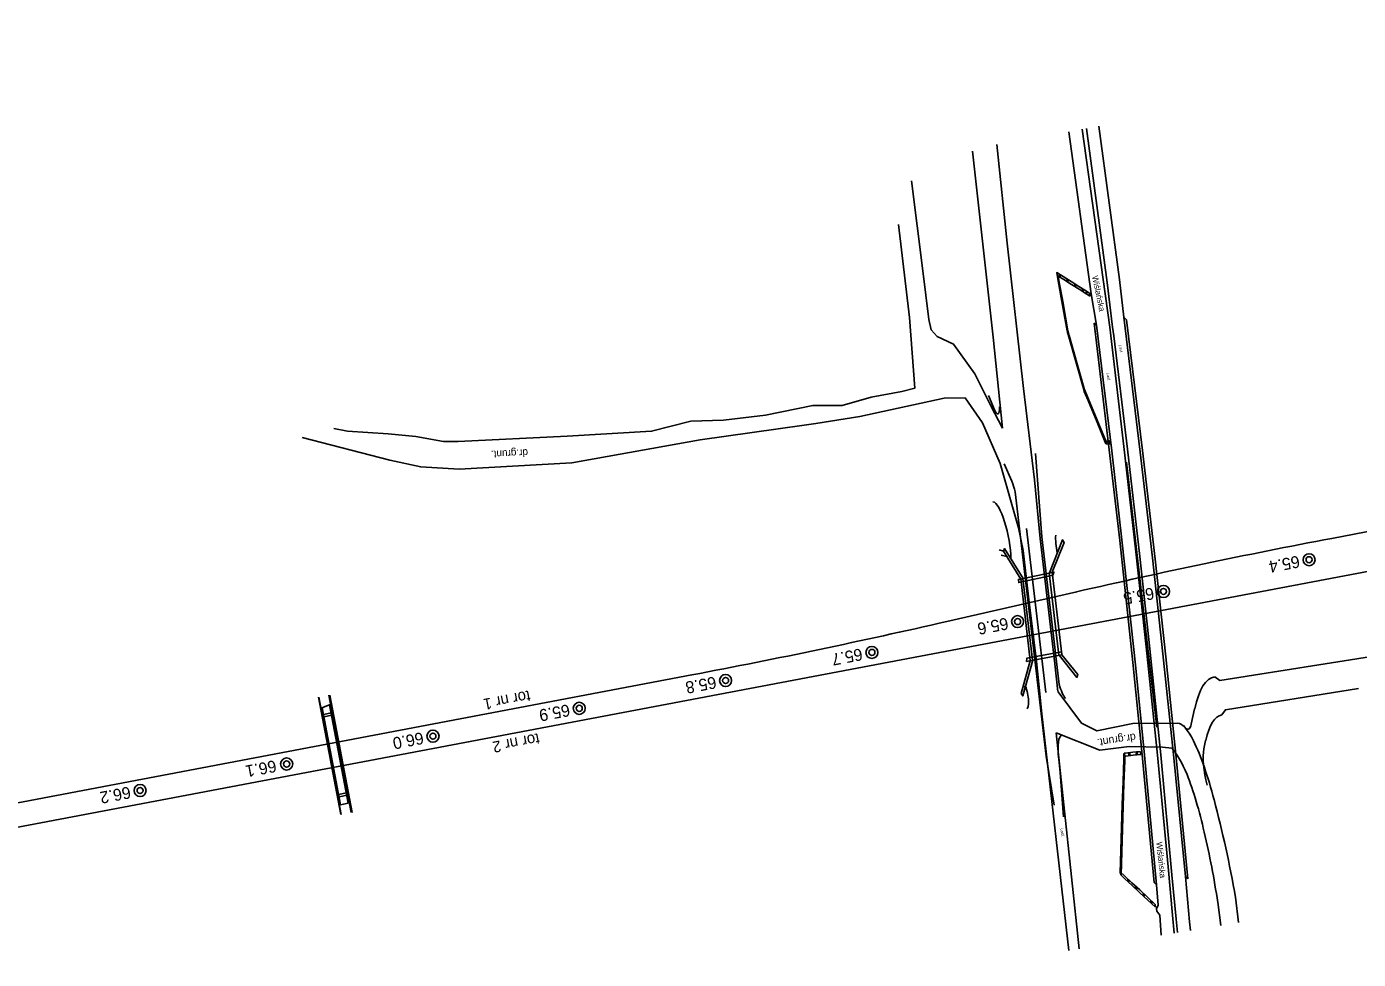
# Model space of a CAD drawing. Extents: x 6541740 to 6556805, y 5525233 to 5530361.
# Drawn here: x 6556027.8 to 6556251.3, y 5525917.2 to 5526073.7 of the extents above; entities that cross this region are included whole.
import ezdxf

# ---------------------------------------------------------------- set-up
doc = ezdxf.new("R2010")
doc.units = 0
for name, color, linetype in [('Default', 7, 'Continuous'), ('TOR_PS_OPIS_T-numeracja torow i rozjazdow', 7, 'Continuous'), ('TOR_SCH-budynki', 7, 'Continuous'), ('TOR_SCH-hektometry', 7, 'Continuous'), ('TOR_SCH-obiekty istniejace', 7, 'Continuous'), ('TOR_SCH-obiekty projektowane', 7, 'Continuous'), ('TOR_SCH-przejazdy+drogi istniejace', 7, 'Continuous'), ('TOR_SCH-przejazdy+drogi projektowane', 7, 'Continuous'), ('TOR_SCH-tory projektowane', 7, 'Continuous')]:
    doc.layers.add(name, color=color, linetype=linetype)

# ---------------------------------------------------------------- blocks, each defined once
blk = doc.blocks.new('4010_1')
at = {"layer": 'Default'}
for radius in [0.75, 0.375]:
    blk.add_circle((0, 0), radius, dxfattribs=at)

msp = doc.modelspace()

# ---------------------------------------------------------------- linework, layer by layer
at = {"layer": 'TOR_SCH-budynki'}
msp.add_line((6556222.71, 5525930.72), (6556222.31, 5525931.11), dxfattribs=at)
at = {"layer": 'TOR_SCH-obiekty istniejace'}
for p, q in [((6556200.84, 5526031.77), (6556201.47, 5526028.22)), ((6556201.13, 5526032.22), (6556201.06, 5526031.81)), ((6556201.31, 5526032.1), (6556201.24, 5526031.7)), ((6556203.1, 5526030.97), (6556201.79, 5526031.79)), ((6556203.18, 5526030.48), (6556201.88, 5526031.3)), ((6556202.43, 5526031.4), (6556202.36, 5526030.99)), ((6556202.61, 5526031.28), (6556202.55, 5526030.88)), ((6556204.41, 5526030.15), (6556203.1, 5526030.97)), ((6556201.14, 5526030.79), (6556201.6, 5526028.22)), ((6556201.2, 5526029.78), (6556201.39, 5526029.38)), ((6556201.29, 5526029.22), (6556201.49, 5526028.82)), ((6556204.48, 5526029.67), (6556203.18, 5526030.48)), ((6556203.73, 5526030.58), (6556203.66, 5526030.18)), ((6556203.91, 5526030.46), (6556203.85, 5526030.06)), ((6556205.71, 5526029.33), (6556204.41, 5526030.15)), ((6556205.77, 5526028.85), (6556204.48, 5526029.67)), ((6556205.03, 5526029.76), (6556204.97, 5526029.36)), ((6556205.22, 5526029.64), (6556205.15, 5526029.24)), ((6556205.77, 5526028.85), (6556205.71, 5526029.33)), ((6556205.71, 5526029.33), (6556206.22, 5526029.02)), ((6556205.71, 5526029.33), (6556205.77, 5526028.85)), ((6556205.77, 5526028.85), (6556206.28, 5526028.53)), ((6556206.28, 5526028.53), (6556206.22, 5526029.02)), ((6556201.6, 5526028.22), (6556201.47, 5526028.22)), ((6556201.58, 5526027.63), (6556201.47, 5526028.22)), ((6556201.47, 5526028.22), (6556201.6, 5526028.22)), ((6556202.44, 5526022.71), (6556201.58, 5526027.63)), ((6556201.7, 5526027.63), (6556201.6, 5526028.22)), ((6556202.57, 5526022.71), (6556201.7, 5526027.63)), ((6556214.73, 5526002.32), (6556211.96, 5526024.97)), ((6556211.96, 5526024.97), (6556212.41, 5526024.54)), ((6556212.41, 5526024.54), (6556215.09, 5526002.62)), ((6556202.57, 5526022.71), (6556202.44, 5526022.71)), ((6556202.55, 5526022.81), (6556202.47, 5526022.62)), ((6556202.73, 5526021.7), (6556202.47, 5526022.62)), ((6556202.81, 5526021.89), (6556202.55, 5526022.81)), ((6556207.39, 5526023.65), (6556206.99, 5526023.99)), ((6556206.99, 5526023.99), (6556209.53, 5526002.74)), ((6556209.94, 5526002.53), (6556207.39, 5526023.65)), ((6556204.02, 5526017.15), (6556202.73, 5526021.7)), ((6556204.1, 5526017.34), (6556202.81, 5526021.89)), ((6556203.43, 5526019.71), (6556203.22, 5526019.98)), ((6556203.61, 5526019.07), (6556203.4, 5526019.33)), ((6556205.31, 5526012.6), (6556204.02, 5526017.15)), ((6556205.39, 5526012.79), (6556204.1, 5526017.34)), ((6556204.72, 5526015.16), (6556204.51, 5526015.43)), ((6556204.9, 5526014.52), (6556204.69, 5526014.78)), ((6556205.39, 5526012.79), (6556205.31, 5526012.6)), ((6556205.37, 5526012.86), (6556205.33, 5526012.53)), ((6556205.97, 5526010.99), (6556205.33, 5526012.53)), ((6556206, 5526011.32), (6556205.37, 5526012.86)), ((6556207.47, 5526007.37), (6556205.97, 5526010.99)), ((6556207.5, 5526007.7), (6556206, 5526011.32)), ((6556206.72, 5526009.59), (6556206.54, 5526009.62)), ((6556206.93, 5526009.07), (6556206.75, 5526009.1)), ((6556208.97, 5526003.74), (6556207.47, 5526007.37)), ((6556209, 5526004.08), (6556207.5, 5526007.7)), ((6556208.22, 5526005.96), (6556208.04, 5526005.99)), ((6556208.43, 5526005.45), (6556208.25, 5526005.48)), ((6556209.57, 5526004.22), (6556208.94, 5526004.15)), ((6556208.94, 5526004.15), (6556209.03, 5526003.66)), ((6556209, 5526004.08), (6556208.97, 5526003.74)), ((6556209.1, 5526004.17), (6556209.06, 5526003.67)), ((6556209.57, 5526004.22), (6556209.66, 5526003.72)), ((6556209.66, 5526003.72), (6556209.03, 5526003.66)), ((6556209.53, 5526002.74), (6556211.27, 5525987.51)), ((6556211.71, 5525987.1), (6556209.94, 5526002.53)), ((6556214.73, 5526002.32), (6556216.78, 5525984.59)), ((6556215.09, 5526002.62), (6556217.2, 5525984.4)), ((6556211.27, 5525987.51), (6556213.47, 5525967.02)), ((6556213.91, 5525966.67), (6556211.71, 5525987.1)), ((6556216.78, 5525984.59), (6556218.54, 5525968.49)), ((6556217.2, 5525984.4), (6556218.99, 5525968)), ((6556218.54, 5525968.49), (6556220.36, 5525951.03)), ((6556213.47, 5525967.02), (6556214.99, 5525952.12)), ((6556215.46, 5525951.48), (6556213.91, 5525966.67)), ((6556218.99, 5525968), (6556220.81, 5525950.49)), ((6556077.35, 5525959.41), (6556078.64, 5525959.96)), ((6556080.47, 5525943.17), (6556077.41, 5525959.42)), ((6556211.83, 5525947.03), (6556211.95, 5525950.86)), ((6556211.95, 5525950.86), (6556211.98, 5525951.74)), ((6556212.14, 5525951.43), (6556211.98, 5525951.74)), ((6556211.99, 5525946.72), (6556212.11, 5525950.55)), ((6556212.22, 5525951.84), (6556212.01, 5525951.82)), ((6556212.01, 5525951.82), (6556212.11, 5525951.33)), ((6556212.11, 5525950.55), (6556212.14, 5525951.43)), ((6556212.31, 5525951.35), (6556212.11, 5525951.33)), ((6556213.47, 5525951.97), (6556212.22, 5525951.84)), ((6556213.56, 5525951.48), (6556212.31, 5525951.35)), ((6556212.82, 5525951.9), (6556212.79, 5525951.4)), ((6556213, 5525951.92), (6556212.96, 5525951.42)), ((6556214.72, 5525952.11), (6556213.47, 5525951.97)), ((6556214.81, 5525951.62), (6556213.56, 5525951.48)), ((6556214.07, 5525952.04), (6556214.03, 5525951.53)), ((6556214.24, 5525952.06), (6556214.21, 5525951.55)), ((6556214.72, 5525952.11), (6556214.81, 5525951.62)), ((6556214.99, 5525952.12), (6556217.04, 5525930.14)), ((6556217.43, 5525929.72), (6556215.46, 5525951.48)), ((6556220.36, 5525951.03), (6556222.31, 5525931.11)), ((6556220.81, 5525950.49), (6556222.71, 5525930.72)), ((6556212.03, 5525948.17), (6556211.89, 5525948.87)), ((6556212.05, 5525948.71), (6556211.91, 5525949.41)), ((6556211.71, 5525943.21), (6556211.83, 5525947.03)), ((6556211.86, 5525942.9), (6556211.99, 5525946.72)), ((6556211.91, 5525944.35), (6556211.77, 5525945.04)), ((6556211.93, 5525944.89), (6556211.79, 5525945.58)), ((6556080.48, 5525943.14), (6556081.77, 5525943.45)), ((6556211.59, 5525939.39), (6556211.71, 5525943.21)), ((6556211.81, 5525941.07), (6556211.66, 5525941.76)), ((6556211.74, 5525939.08), (6556211.86, 5525942.9)), ((6556211.47, 5525935.56), (6556211.59, 5525939.39)), ((6556211.79, 5525940.53), (6556211.65, 5525941.22)), ((6556211.67, 5525936.7), (6556211.53, 5525937.4)), ((6556211.68, 5525937.24), (6556211.54, 5525937.94)), ((6556211.62, 5525935.25), (6556211.74, 5525939.08)), ((6556211.35, 5525931.74), (6556211.47, 5525935.56)), ((6556211.5, 5525931.43), (6556211.62, 5525935.25)), ((6556211.55, 5525932.88), (6556211.4, 5525933.57)), ((6556211.56, 5525933.42), (6556211.42, 5525934.11)), ((6556211.5, 5525931.43), (6556211.35, 5525931.74)), ((6556211.4, 5525931.88), (6556211.45, 5525931.41)), ((6556212.04, 5525931.28), (6556211.4, 5525931.88)), ((6556212.09, 5525930.81), (6556211.45, 5525931.41)), ((6556213.33, 5525930.07), (6556212.04, 5525931.28)), ((6556213.38, 5525929.6), (6556212.09, 5525930.81)), ((6556212.66, 5525930.7), (6556212.58, 5525930.35)), ((6556212.84, 5525930.53), (6556212.76, 5525930.18)), ((6556214.63, 5525928.87), (6556213.33, 5525930.07)), ((6556214.67, 5525928.4), (6556213.38, 5525929.6)), ((6556213.95, 5525929.5), (6556213.87, 5525929.14)), ((6556214.14, 5525929.33), (6556214.05, 5525928.97)), ((6556215.92, 5525927.66), (6556214.63, 5525928.87)), ((6556215.97, 5525927.19), (6556214.67, 5525928.4)), ((6556215.25, 5525928.29), (6556215.16, 5525927.94)), ((6556215.43, 5525928.12), (6556215.35, 5525927.77)), ((6556217.04, 5525930.14), (6556217.43, 5525929.72)), ((6556217.21, 5525926.46), (6556215.92, 5525927.66)), ((6556217.26, 5525925.98), (6556215.97, 5525927.19)), ((6556216.54, 5525927.08), (6556216.46, 5525926.73)), ((6556216.72, 5525926.91), (6556216.64, 5525926.56)), ((6556217.21, 5525926.46), (6556217.26, 5525925.98))]:
    msp.add_line(p, q, dxfattribs=at)
for points in [[(6556201.79, 5526031.79), (6556200.71, 5526032.47), (6556200.84, 5526031.77)], [(6556201.88, 5526031.3), (6556200.95, 5526031.88), (6556201.14, 5526030.79)], [(6556080.46, 5525943.17), (6556080.33, 5525943.4), (6556077.35, 5525959.41), (6556077.39, 5525959.42)], [(6556081.77, 5525943.45), (6556081.81, 5525943.73), (6556078.72, 5525959.93), (6556078.64, 5525959.96)], [(6556081.77, 5525943.45), (6556078.64, 5525959.96), (6556078.72, 5525959.93)]]:
    msp.add_lwpolyline(points, dxfattribs=at)
at = {"layer": 'TOR_SCH-obiekty projektowane'}
for p, q in [((6556212.44, 5526000.66), (6556217.48, 5525956.17)), ((6556198.87, 5525961.98), (6556195.65, 5525989.51)), ((6556191.04, 5525985.97), (6556191.77, 5525985.74)), ((6556191.39, 5525985.06), (6556192.34, 5525984.81)), ((6556199.44, 5525982.09), (6556201.06, 5525968.28)), ((6556199.92, 5525982.19), (6556201.54, 5525968.37)), ((6556195.08, 5525962.98), (6556195.41, 5525963.04)), ((6556077.34, 5525958.27), (6556079.26, 5525958.64)), ((6556077.42, 5525957.88), (6556079.33, 5525958.24)), ((6556079.88, 5525944.86), (6556081.8, 5525945.23)), ((6556079.96, 5525944.47), (6556081.87, 5525944.83))]:
    msp.add_line(p, q, dxfattribs=at)
for points in [[(6556195.05, 5525981.11), (6556191.92, 5525986.15), (6556191.76, 5525985.74), (6556194.68, 5525981.04)], [(6556199.95, 5525982.19), (6556201.94, 5525987.2), (6556201.67, 5525987.63), (6556199.47, 5525982.1)], [(6556194.67, 5525981.06), (6556196.27, 5525967.35)], [(6556195.04, 5525981.12), (6556196.65, 5525967.41)], [(6556201.54, 5525968.34), (6556204.22, 5525965), (6556204.1, 5525964.53), (6556201.12, 5525968.26)], [(6556196.27, 5525967.34), (6556194.71, 5525961.82), (6556195, 5525961.44), (6556196.69, 5525967.42)], [(6556078.7, 5525961.58), (6556082.43, 5525941.89)], [(6556076.78, 5525961.22), (6556080.52, 5525941.52)], [(6556076.86, 5525961.23), (6556080.59, 5525941.54)], [(6556078.53, 5525961.55), (6556082.27, 5525941.86)]]:
    msp.add_lwpolyline(points, dxfattribs=at)
for points in [[(6556200.13, 5525981.68), (6556194.32, 5525980.46), (6556194.28, 5525980.98), (6556200.23, 5525982.21)], [(6556201.58, 5525968.35), (6556195.63, 5525967.22), (6556195.66, 5525967.74), (6556201.48, 5525968.84)]]:
    msp.add_lwpolyline(points, close=True, dxfattribs=at)
for centre, major_axis, start_param, end_param in [((6556191.04, 5525987.73), (-1.19, 6.29), 4.108348, 6.190214), ((6556201.83, 5525985.59), (-0.79, 4.17), 0.786258, 1.565177), ((6556195.25, 5525961.58), (-0.44, 2.31), 3.121936, 5.354257)]:
    msp.add_ellipse(centre, major_axis=major_axis, ratio=0.25, start_param=start_param, end_param=end_param, dxfattribs=at)
at = {"layer": 'TOR_SCH-przejazdy+drogi istniejace'}
for p, q in [((6556206.5, 5526028.89), (6556202.71, 5526056.1)), ((6556204.95, 5526056.51), (6556208.52, 5526031.33)), ((6556209.19, 5526030.79), (6556205.68, 5526056.64)), ((6556207.77, 5526057.01), (6556211.24, 5526031.31)), ((6556190.64, 5526053.95), (6556192.4, 5526037.4)), ((6556190.05, 5526021.62), (6556186.57, 5526052.81)), ((6556178.22, 5526032.76), (6556176.34, 5526047.84)), ((6556176, 5526024.94), (6556174.15, 5526040.51)), ((6556192.4, 5526037.4), (6556195.1, 5526013)), ((6556208.52, 5526031.33), (6556209.6, 5526023.3)), ((6556211.24, 5526031.31), (6556211.96, 5526024.97)), ((6556207.39, 5526023.65), (6556206.5, 5526028.89)), ((6556210.05, 5526023.29), (6556209.19, 5526030.79)), ((6556202.12, 5526025.27), (6556201.91, 5526025.77)), ((6556202.24, 5526024.58), (6556202.03, 5526025.07)), ((6556211.96, 5526024.97), (6556214.73, 5526002.32)), ((6556209.94, 5526002.53), (6556207.39, 5526023.65)), ((6556209.6, 5526023.3), (6556209.77, 5526021.85)), ((6556210.29, 5526021.85), (6556210.05, 5526023.29)), ((6556191.62, 5526006.36), (6556190.05, 5526021.62)), ((6556209.77, 5526021.85), (6556211.98, 5526003.27)), ((6556212.56, 5526002.83), (6556210.29, 5526021.85)), ((6556195.1, 5526013), (6556196.99, 5525997.69)), ((6556088.78, 5526001.01), (6556074.03, 5526004.77)), ((6556211.71, 5525987.1), (6556209.94, 5526002.53)), ((6556211.98, 5526003.27), (6556213.99, 5525985.59)), ((6556214.63, 5525984.85), (6556212.56, 5526002.83)), ((6556213.91, 5525966.67), (6556211.71, 5525987.1)), ((6556213.99, 5525985.59), (6556215.74, 5525969.65)), ((6556216.32, 5525969.31), (6556214.63, 5525984.85)), ((6556215.74, 5525969.65), (6556217.61, 5525951.49)), ((6556218.17, 5525951.56), (6556216.32, 5525969.31)), ((6556215.46, 5525951.48), (6556213.91, 5525966.67)), ((6556204.85, 5525956.86), (6556200.94, 5525962.11)), ((6556202.73, 5525918.72), (6556198.21, 5525958.42)), ((6556200.61, 5525955.22), (6556207.91, 5525952.31)), ((6556200.61, 5525955.22), (6556204.47, 5525919)), ((6556207.41, 5525955.59), (6556204.85, 5525956.86)), ((6556213.47, 5525956.83), (6556207.41, 5525955.59)), ((6556221.01, 5525956.88), (6556213.47, 5525956.83)), ((6556207.91, 5525952.31), (6556212.88, 5525952.93)), ((6556212.88, 5525952.93), (6556218.43, 5525952.82)), ((6556218.43, 5525952.82), (6556220.03, 5525952.69)), ((6556217.43, 5525929.72), (6556215.46, 5525951.48)), ((6556217.61, 5525951.49), (6556219.41, 5525932.73)), ((6556220.04, 5525931.43), (6556218.17, 5525951.56)), ((6556219.41, 5525932.73), (6556220.14, 5525924.63)), ((6556220.75, 5525923.98), (6556220.04, 5525931.43)), ((6556222.31, 5525931.11), (6556223, 5525923.52)), ((6556217.75, 5525926.31), (6556217.43, 5525929.72)), ((6556217.45, 5525925.73), (6556217.75, 5525926.31)), ((6556227.73, 5525926.8), (6556228.22, 5525922.91)), ((6556231.23, 5525923.41), (6556230.69, 5525927.64)), ((6556217.48, 5525925.29), (6556217.45, 5525925.73)), ((6556217.99, 5525924.63), (6556217.48, 5525925.29)), ((6556217.99, 5525924.63), (6556218.23, 5525921.27)), ((6556220.4, 5525921.63), (6556220.14, 5525924.63)), ((6556220.75, 5525923.98), (6556220.97, 5525921.72)), ((6556223.18, 5525922.08), (6556223, 5525923.52))]:
    msp.add_line(p, q, dxfattribs=at)
for points in [[(6556178.22, 5526032.76), (6556179.24, 5526024.57), (6556179.65, 5526022.85), (6556180.62, 5526021.73), (6556183.4, 5526020.47), (6556186.97, 5526015.5), (6556189.65, 5526010.11), (6556191.62, 5526006.36)], [(6556139.28, 5526007.55), (6556144.77, 5526007.7), (6556151.83, 5526008.55), (6556159.79, 5526010.18), (6556164.68, 5526010.15), (6556169.56, 5526011.55), (6556174.7, 5526012.53), (6556176.88, 5526013.06), (6556176.88, 5526013.06), (6556176, 5526024.94)], [(6556194.3, 5525989.63), (6556191.2, 5526000.42), (6556188.25, 5526007.25), (6556185.31, 5526011.45), (6556181.83, 5526011.4), (6556176.64, 5526010.25), (6556167.64, 5526008.31), (6556160.27, 5526007.15), (6556158.31, 5526006.89), (6556140.84, 5526004.39), (6556140.84, 5526004.39), (6556119.33, 5526000.56)], [(6556079.34, 5526006.3), (6556081.66, 5526005.88), (6556088.46, 5526005.42)], [(6556139.28, 5526007.55), (6556132.69, 5526005.85), (6556118.51, 5526005.04), (6556100.23, 5526004.11), (6556097.77, 5526004.13), (6556093.15, 5526004.96), (6556088.46, 5526005.42)], [(6556119.33, 5526000.56), (6556100.42, 5525999.46), (6556093.95, 5525999.85), (6556088.78, 5526001.01)], [(6556196.99, 5525997.69), (6556197.93, 5525987.84), (6556200.39, 5525966.8), (6556200.39, 5525966.8), (6556200.39, 5525966.8)], [(6556198.21, 5525958.42), (6556197.87, 5525961.76), (6556197.3, 5525967.2), (6556195.99, 5525978.06), (6556195.05, 5525985.86), (6556194.3, 5525989.63)], [(6556200.39, 5525966.8), (6556200.9, 5525962.15)]]:
    msp.add_lwpolyline(points, dxfattribs=at)
for centre, major_axis, start_param, end_param in [((6556223.36, 5525943.26), (-2.58, 13.6), 5.563684, 6.218308), ((6556221.43, 5525935.17), (-3.55, 18.71), 5.438089, 5.874166), ((6556222.98, 5525937.74), (-4.02, 21.2), 4.965561, 5.531031), ((6556220.84, 5525935.04), (-3.89, 20.54), 4.837395, 5.362942), ((6556218.38, 5525928.39), (-8.93, 47.11), 4.649079, 5.00294), ((6556217.98, 5525930.54), (-6.69, 35.31), 4.55901, 4.893976)]:
    msp.add_ellipse(centre, major_axis=major_axis, ratio=0.25, start_param=start_param, end_param=end_param, dxfattribs=at)
at = {"layer": 'TOR_SCH-przejazdy+drogi projektowane'}
for p, q in [((6556189.24, 5526011.84), (6556190.26, 5526009.42)), ((6556197.12, 5526002.13), (6556198.19, 5525988.13)), ((6556191.9, 5526000.39), (6556193.15, 5525997.45)), ((6556193.75, 5525995.65), (6556198.95, 5525951.31)), ((6556198.19, 5525988.13), (6556201.1, 5525963.34)), ((6556255.66, 5525968.41), (6556228.1, 5525964.02)), ((6556228.1, 5525964.02), (6556227.22, 5525964.63)), ((6556223.85, 5525959.29), (6556223.29, 5525956.7)), ((6556225.7, 5525953.95), (6556225.4, 5525952.54)), ((6556198.95, 5525951.31), (6556200.3, 5525943.12)), ((6556201.03, 5525950.84), (6556201.3, 5525948.56)), ((6556201.84, 5525941.15), (6556201.3, 5525948.56))]:
    msp.add_line(p, q, dxfattribs=at)
msp.add_lwpolyline([(6556251.33, 5525962.66), (6556229.03, 5525959.1), (6556228.42, 5525958.25)], dxfattribs=at)
for centre, major_axis, start_param, end_param in [((6556190.41, 5526010.94), (0.42, -2.21), 5.42306, 7.345784), ((6556192.84, 5525994.04), (-0.93, 4.91), 4.998843, 5.431266), ((6556233.34, 5525931.95), (-6.19, 32.67), 6.27356, 6.81674), ((6556201.87, 5525965.71), (0.98, -5.16), 5.141045, 5.808868), ((6556233.34, 5525931.95), (-4.98, 26.28), 6.27302, 6.81674), ((6556221.79, 5525961.01), (0.98, -5.16), 5.740187, 6.81674), ((6556202.54, 5525949.67), (-0.98, 5.16), 6.266936, 7.57809), ((6556226.9, 5525948.22), (-0.98, 5.16), 0.533555, 1.868194)]:
    msp.add_ellipse(centre, major_axis=major_axis, ratio=0.25, start_param=start_param, end_param=end_param, dxfattribs=at)
at = {"layer": 'TOR_SCH-tory projektowane'}
for p, q in [((6556735.03, 5526073.73), (6555909.41, 5525917.23)), ((6556281.77, 5525994.48), (6556246.88, 5525987.87)), ((6556204.05, 5525978.9), (6556182.28, 5525973.92)), ((6556139.45, 5525964.96), (6555970.25, 5525932.89))]:
    msp.add_line(p, q, dxfattribs=at)
for centre, start_param, end_param in [((6559692.26, 5507811.53), 0, 0.00946), ((6552694.07, 5544141.3), 3.141593, 3.151053)]:
    msp.add_ellipse(centre, major_axis=(-3445.38, 18176.34), ratio=0.25, start_param=start_param, end_param=end_param, dxfattribs=at)

# ---------------------------------------------------------------- block references
at = {"layer": 'TOR_SCH-hektometry', "xscale": 1.345963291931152, "yscale": 1.345963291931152}
for p in [(6556243.06, 5525984.29), (6556218.62, 5525978.96), (6556194.14, 5525973.9), (6556169.68, 5525968.73), (6556145.13, 5525964.02), (6556120.57, 5525959.35), (6556096.01, 5525954.68), (6556071.45, 5525950.01), (6556046.85, 5525945.56)]:
    msp.add_blockref('4010_1', p, dxfattribs=at)

# ---------------------------------------------------------------- texts
at = {"layer": 'TOR_PS_OPIS_T-numeracja torow i rozjazdow'}
for s, p in [('tor nr 1', (6556112.15, 5525962.37)), ('tor nr 2', (6556113.7, 5525955.19))]:
    msp.add_text(s, height=1.875, rotation=190.7101, dxfattribs=at).set_placement(p)
at = {"layer": 'TOR_SCH-hektometry'}
for s, p in [('65.4', (6556241.28, 5525985)), ('65.5', (6556216.85, 5525979.67)), ('65.6', (6556192.37, 5525974.6)), ('65.7', (6556167.9, 5525969.44)), ('65.8', (6556143.36, 5525964.72)), ('65.9', (6556118.79, 5525960.06)), ('66.0', (6556094.23, 5525955.38)), ('66.1', (6556069.52, 5525950.68)), ('66.2', (6556045.07, 5525946.26))]:
    msp.add_text(s, height=2, rotation=190.7691, dxfattribs=at).set_placement(p)
at = {"layer": 'TOR_SCH-przejazdy+drogi istniejace'}
for s, height, rotation, p in [('Wiślańska', 1, 281.886, (6556206.62, 5526031.83)), ('j.asf.', 0.454, 276.6965, (6556211.18, 5526020.25)), ('j.asf.', 0.454, 276.6981, (6556209.08, 5526015.54)), ('dr.grunt.', 1.25, 182.7794, (6556111.93, 5526002.85)), ('dr.grunt.', 1.318, 188.4251, (6556213.88, 5525955.15)), ('j.asf.', 0.481, 276.1947, (6556201.34, 5525939.17)), ('Wiślańska', 1, 275.8941, (6556217.41, 5525936.89))]:
    msp.add_text(s, height=height, rotation=rotation, dxfattribs=at).set_placement(p)

doc.saveas('drawing.dxf')
